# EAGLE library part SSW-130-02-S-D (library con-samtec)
THROUGH-HOLE .025" SQ POST SOCKET Source: Samtec SSW.pdf
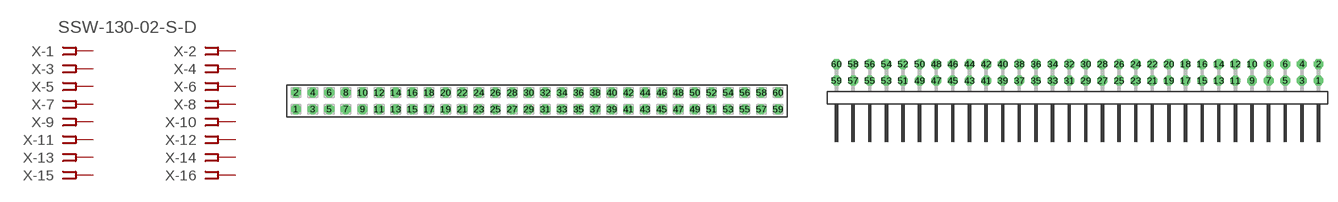
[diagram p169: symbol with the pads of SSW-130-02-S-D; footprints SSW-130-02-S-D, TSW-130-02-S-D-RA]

Designator prefix X; gates -1=FPINV -2=FPIN -3=FPIN -4=FPIN -5=FPIN -6=FPIN -7=FPIN -8=FPIN -9=FPIN -10=FPIN -11=FPIN -12=FPIN -13=FPIN -14=FPIN -15=FPIN -16=FPIN -17=FPIN -18=FPIN -19=FPIN -20=FPIN -21=FPIN -22=FPIN -23=FPIN -24=FPIN -25=FPIN -26=FPIN -27=FPIN -28=FPIN -29=FPIN -30=FPIN -31=FPIN -32=FPIN -33=FPIN -34=FPIN -35=FPIN -36=FPIN -37=FPIN -38=FPIN -39=FPIN -40=FPIN -41=FPIN -42=FPIN -43=FPIN -44=FPIN -45=FPIN -46=FPIN -47=FPIN -48=FPIN -49=FPIN -50=FPIN -51=FPIN -52=FPIN -53=FPIN -54=FPIN -55=FPIN -56=FPIN -57=FPIN -58=FPIN -59=FPIN -60=FPIN

## SSW-130-02-S-D (MPN: SSW-130-02-S-D; OC_FARNELL: unknown; OC_NEWARK: 11P9804)  [SSW-130-02-S-D]
1  -1:1  pas
2  -2:1  pas
3  -3:1  pas
4  -4:1  pas
5  -5:1  pas
6  -6:1  pas
7  -7:1  pas
8  -8:1  pas
9  -9:1  pas
10  -10:1  pas
11  -11:1  pas
12  -12:1  pas
13  -13:1  pas
14  -14:1  pas
15  -15:1  pas
16  -16:1  pas
17  -17:1  pas
18  -18:1  pas
19  -19:1  pas
20  -20:1  pas
21  -21:1  pas
22  -22:1  pas
23  -23:1  pas
24  -24:1  pas
25  -25:1  pas
26  -26:1  pas
27  -27:1  pas
28  -28:1  pas
29  -29:1  pas
30  -30:1  pas
31  -31:1  pas
32  -32:1  pas
33  -33:1  pas
34  -34:1  pas
35  -35:1  pas
36  -36:1  pas
37  -37:1  pas
38  -38:1  pas
39  -39:1  pas
40  -40:1  pas
41  -41:1  pas
42  -42:1  pas
43  -43:1  pas
44  -44:1  pas
45  -45:1  pas
46  -46:1  pas
47  -47:1  pas
48  -48:1  pas
49  -49:1  pas
50  -50:1  pas
51  -51:1  pas
52  -52:1  pas
53  -53:1  pas
54  -54:1  pas
55  -55:1  pas
56  -56:1  pas
57  -57:1  pas
58  -58:1  pas
59  -59:1  pas
60  -60:1  pas

## SSW-130-02-S-D-RA (MPN: SSW-130-02-S-D-RA; OC_FARNELL: unknown; OC_NEWARK: 11P9805)  [TSW-130-02-S-D-RA]
Pads as for SSW-130-02-S-D

## Footprint SSW-130-02-S-D (pad centres in mm)
THROUGH-HOLE .025" SQ POST SOCKET Source: Samtec SSW.pdf
drill 1 pad 1.5 octagon: 1 -36.83,-1.27; 2 -36.83,1.27; 3 -34.29,-1.27; 4 -34.29,1.27; 5 -31.75,-1.27; 6 -31.75,1.27; 7 -29.21,-1.27; 8 -29.21,1.27; 9 -26.67,-1.27; 10 -26.67,1.27; 11 -24.13,-1.27; 12 -24.13,1.27; 13 -21.59,-1.27; 14 -21.59,1.27; 15 -19.05,-1.27; 16 -19.05,1.27; 17 -16.51,-1.27; 18 -16.51,1.27; 19 -13.97,-1.27; 20 -13.97,1.27; 21 -11.43,-1.27; 22 -11.43,1.27; 23 -8.89,-1.27; 24 -8.89,1.27; 25 -6.35,-1.27; 26 -6.35,1.27; 27 -3.81,-1.27; 28 -3.81,1.27; 29 -1.27,-1.27; 30 -1.27,1.27; 31 1.27,-1.27; 32 1.27,1.27; 33 3.81,-1.27; 34 3.81,1.27; 35 6.35,-1.27; 36 6.35,1.27; 37 8.89,-1.27; 38 8.89,1.27; 39 11.43,-1.27; 40 11.43,1.27; 41 13.97,-1.27; 42 13.97,1.27; 43 16.51,-1.27; 44 16.51,1.27; 45 19.05,-1.27; 46 19.05,1.27; 47 21.59,-1.27; 48 21.59,1.27; 49 24.13,-1.27; 50 24.13,1.27; 51 26.67,-1.27; 52 26.67,1.27; 53 29.21,-1.27; 54 29.21,1.27; 55 31.75,-1.27; 56 31.75,1.27; 57 34.29,-1.27; 58 34.29,1.27; 59 36.83,-1.27; 60 36.83,1.27

## Footprint TSW-130-02-S-D-RA (pad centres in mm)
THROUGH-HOLE .025" SQ POST HEADER Source: Samtec TSW.pdf
drill 1 pad 1.5 octagon: 1 36.83,1.524; 2 36.83,4.064; 3 34.29,1.524; 4 34.29,4.064; 5 31.75,1.524; 6 31.75,4.064; 7 29.21,1.524; 8 29.21,4.064; 9 26.67,1.524; 10 26.67,4.064; 11 24.13,1.524; 12 24.13,4.064; 13 21.59,1.524; 14 21.59,4.064; 15 19.05,1.524; 16 19.05,4.064; 17 16.51,1.524; 18 16.51,4.064; 19 13.97,1.524; 20 13.97,4.064; 21 11.43,1.524; 22 11.43,4.064; 23 8.89,1.524; 24 8.89,4.064; 25 6.35,1.524; 26 6.35,4.064; 27 3.81,1.524; 28 3.81,4.064; 29 1.27,1.524; 30 1.27,4.064; 31 -1.27,1.524; 32 -1.27,4.064; 33 -3.81,1.524; 34 -3.81,4.064; 35 -6.35,1.524; 36 -6.35,4.064; 37 -8.89,1.524; 38 -8.89,4.064; 39 -11.43,1.524; 40 -11.43,4.064; 41 -13.97,1.524; 42 -13.97,4.064; 43 -16.51,1.524; 44 -16.51,4.064; 45 -19.05,1.524; 46 -19.05,4.064; 47 -21.59,1.524; 48 -21.59,4.064; 49 -24.13,1.524; 50 -24.13,4.064; 51 -26.67,1.524; 52 -26.67,4.064; 53 -29.21,1.524; 54 -29.21,4.064; 55 -31.75,1.524; 56 -31.75,4.064; 57 -34.29,1.524; 58 -34.29,4.064; 59 -36.83,1.524; 60 -36.83,4.064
